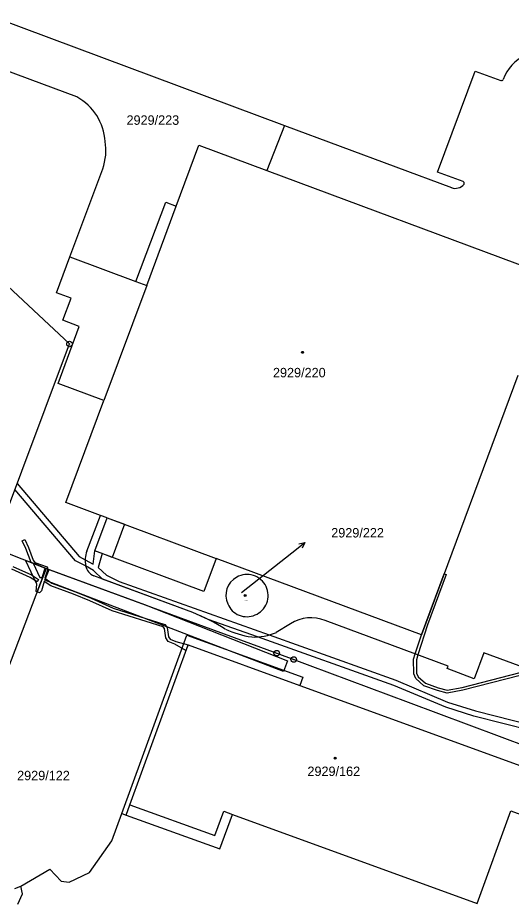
# Model space of a CAD drawing. Extents: x -593183 to -588034, y -1130415 to -1124994.
# Drawn here: x -591765.5 to -591676.7, y -1128297.1 to -1128137.6 of the extents above; entities that cross this region are included whole.
import ezdxf

# ---------------------------------------------------------------- set-up
doc = ezdxf.new("R2010")
doc.units = 0
for name, color, linetype in [('Vrstva 1', 7, 'Continuous'), ('Vrstva 16', 7, 'Continuous'), ('Vrstva 18', 7, 'Continuous'), ('Vrstva 19', 7, 'Continuous'), ('Vrstva 24', 7, 'Continuous'), ('Vrstva 25', 7, 'Continuous'), ('Vrstva 27', 7, 'Continuous'), ('Vrstva 4', 7, 'Continuous')]:
    doc.layers.add(name, color=color, linetype=linetype)

msp = doc.modelspace()

# ---------------------------------------------------------------- linework, layer by layer
at = {"layer": 'Vrstva 1'}
for p, q in [((-591717.5, -1128157.01), (-591720.69, -1128165.1)), ((-591717.5, -1128157.01), (-591687.51, -1128168.17)), ((-591717.5, -1128157.01), (-591687.51, -1128168.17)), ((-591717.5, -1128157.01), (-591687.51, -1128168.17)), ((-591737, -1128171.48), (-591732.94, -1128160.55)), ((-591732.94, -1128160.55), (-591720.69, -1128165.1)), ((-591756.14, -1128180.6), (-591750.22, -1128164.77)), ((-591756.14, -1128180.6), (-591750.22, -1128164.77)), ((-591756.14, -1128180.6), (-591750.22, -1128164.77)), ((-591720.69, -1128165.1), (-591669, -1128184.32)), ((-591782.19, -1128171.99), (-591756.21, -1128196.29)), ((-591758.54, -1128187.07), (-591756.14, -1128180.6)), ((-591756.14, -1128180.6), (-591744.27, -1128185.05)), ((-591755.89, -1128188.03), (-591758.54, -1128187.07)), ((-591757.38, -1128192.01), (-591755.89, -1128188.03)), ((-591754.44, -1128193.13), (-591757.38, -1128192.01)), ((-591758.22, -1128203.42), (-591754.44, -1128193.13)), ((-591769.95, -1128232.86), (-591756.21, -1128196.29)), ((-591675.56, -1128201.97), (-591692.89, -1128248.59)), ((-591750.02, -1128206.47), (-591758.22, -1128203.42)), ((-591756.84, -1128224.81), (-591750.02, -1128206.47)), ((-591750.6, -1128227.13), (-591756.84, -1128224.81)), ((-591753.08, -1128233.56), (-591750.6, -1128227.13)), ((-591751.66, -1128233.51), (-591749.41, -1128227.57)), ((-591749.41, -1128227.57), (-591750.6, -1128227.13)), ((-591769.95, -1128232.86), (-591760.42, -1128236.65)), ((-591732.03, -1128240.78), (-591751.66, -1128233.51)), ((-591729.84, -1128234.85), (-591732.03, -1128240.78)), ((-591692.89, -1128248.59), (-591729.84, -1128234.85)), ((-591768.44, -1128257.8), (-591760.42, -1128236.65)), ((-591760.42, -1128236.65), (-591718.92, -1128251.9)), ((-591733.99, -1128244.6), (-591751.81, -1128237.99)), ((-591733.99, -1128244.6), (-591751.81, -1128237.99)), ((-591733.99, -1128244.6), (-591751.81, -1128237.99)), ((-591716.43, -1128246.62), (-591719, -1128248.15)), ((-591716.43, -1128246.62), (-591719, -1128248.15)), ((-591716.43, -1128246.62), (-591719, -1128248.15)), ((-591716.43, -1128246.62), (-591719, -1128248.15)), ((-591745.34, -1128279.16), (-591734.87, -1128250.37)), ((-591734.87, -1128250.37), (-591714.78, -1128257.68)), ((-591718.92, -1128251.9), (-591715.86, -1128253.03)), ((-591715.86, -1128253.03), (-591712.99, -1128254.1)), ((-591712.99, -1128254.1), (-591695.28, -1128260.71)), ((-591714.78, -1128257.68), (-591668.38, -1128274.57)), ((-591695.28, -1128260.71), (-591673.48, -1128268.84)), ((-591746, -1128281.02), (-591745.34, -1128279.16)), ((-591748.57, -1128285.65), (-591746.78, -1128280.75)), ((-591746.78, -1128280.75), (-591746, -1128281.02)), ((-591746, -1128281.02), (-591729.15, -1128287.1)), ((-591729.15, -1128287.1), (-591726.89, -1128280.89)), ((-591726.89, -1128280.89), (-591682.86, -1128296.9)), ((-591682.86, -1128296.9), (-591676.8, -1128280.25)), ((-591676.8, -1128280.25), (-591671.21, -1128282.28)), ((-591752.63, -1128291.33), (-591748.57, -1128285.65)), ((-591764.94, -1128293.8), (-591759.76, -1128290.74)), ((-591759.76, -1128290.74), (-591757.68, -1128292.92)), ((-591756.24, -1128293.08), (-591752.63, -1128291.33)), ((-591764.68, -1128295.18), (-591764.94, -1128293.8)), ((-591757.68, -1128292.92), (-591756.24, -1128293.08)), ((-591765.52, -1128297.05), (-591764.68, -1128295.18))]:
    msp.add_line(p, q, dxfattribs=at)
for points in [[(-591754.86, -1128151.86), (-591772.23, -1128145.44), (-591769.48, -1128137.62), (-591717.5, -1128157.01)], [(-591685.4, -1128167.09), (-591689.98, -1128165.38), (-591683.2, -1128147.21), (-591678.61, -1128148.88)], [(-591685.4, -1128167.09), (-591689.98, -1128165.38), (-591683.2, -1128147.21), (-591678.61, -1128148.88)], [(-591685.4, -1128167.09), (-591689.98, -1128165.38), (-591683.2, -1128147.21), (-591678.61, -1128148.88)], [(-591744.27, -1128185.05), (-591738.9, -1128170.78), (-591737, -1128171.48)], [(-591744.27, -1128185.05), (-591738.9, -1128170.78), (-591737, -1128171.48)], [(-591744.27, -1128185.05), (-591738.9, -1128170.78), (-591737, -1128171.48)], [(-591744.27, -1128185.05), (-591738.9, -1128170.78), (-591737, -1128171.48)], [(-591744.27, -1128185.05), (-591738.9, -1128170.78), (-591737, -1128171.48)], [(-591681.67, -1128251.81), (-591683.41, -1128256.51), (-591688.27, -1128254.67), (-591688.09, -1128254.23), (-591710.22, -1128246.02)], [(-591681.67, -1128251.81), (-591683.41, -1128256.51), (-591688.27, -1128254.67), (-591688.09, -1128254.23), (-591710.22, -1128246.02)], [(-591640.13, -1128262.72), (-591641.52, -1128266.6), (-591681.67, -1128251.81)]]:
    msp.add_lwpolyline(points, dxfattribs=at)
for centre, radius, start, end in [((-591670.96, -1128151.26), 7.63, 71.7031, 160.6605), ((-591678.46, -1128148.58), 0.334, 243.1252, 333.7447), ((-591759.72, -1128160.54), 9.95, 3.8368, 60.7252), ((-591759.08, -1128161.54), 9.42, 339.9772, 10.2246), ((-591686.8, -1128166.29), 2.02, 249.2737, 321.4904), ((-591685.55, -1128167.41), 0.352, 338.3496, 65.2533), ((-591748.18, -1128235.31), 5.2, 160.3488, 189.6174), ((-591750.78, -1128235.61), 2.6, 192.7529, 246.5462), ((-591724.4, -1128241.45), 3.66, 118.1946, 205.3658), ((-591724.29, -1128241.59), 3.84, 25.8117, 118.6205), ((-591724.24, -1128241.53), 3.77, 292.1424, 25.2266), ((-591724.32, -1128241.7), 3.64, 201.2527, 294.2583), ((-591746.66, -1128276.61), 34.42, 57.5185, 68.4102), ((-591712.76, -1128252.2), 6.68, 67.6979, 123.3395), ((-591720.85, -1128231.64), 17.53, 245.3252, 261.5427), ((-591722.98, -1128239.12), 9.87, 267.4105, 293.8132)]:
    msp.add_arc(centre, radius, start, end, dxfattribs=at)
at = {"layer": 'Vrstva 16'}
msp.add_line((-591725.26, -1128240.98), (-591716.21, -1128233.85), dxfattribs=at)
at = {"layer": 'Vrstva 24'}
for centre, radius in [((-591756.21, -1128196.29), 0.5), ((-591756.21, -1128196.29), 0.0327), ((-591718.92, -1128251.9), 0.5), ((-591718.92, -1128251.9), 0.0327), ((-591715.86, -1128253.03), 0.5), ((-591715.86, -1128253.03), 0.0327)]:
    msp.add_circle(centre, radius, dxfattribs=at)
at = {"layer": 'Vrstva 25'}
msp.add_line((-591716.21, -1128233.85), (-591713.85, -1128231.99), dxfattribs=at)
msp.add_lwpolyline([(-591714.95, -1128232.22), (-591713.85, -1128231.99), (-591714.33, -1128233)], dxfattribs=at)
for centre, radius in [((-591714.27, -1128197.79), 0.175), ((-591714.27, -1128197.79), 0.15), ((-591724.6, -1128241.54), 0.175), ((-591724.6, -1128241.54), 0.15), ((-591708.43, -1128270.76), 0.175), ((-591708.43, -1128270.76), 0.15)]:
    msp.add_circle(centre, radius, dxfattribs=at)
at = {"layer": 'Vrstva 27'}
for p, q in [((-591765.64, -1128221.39), (-591754.49, -1128234.49)), ((-591755.13, -1128235.27), (-591766.04, -1128222.46)), ((-591751.66, -1128233.51), (-591749.41, -1128227.57)), ((-591749.41, -1128227.57), (-591746.32, -1128228.72)), ((-591746.32, -1128228.72), (-591748.52, -1128234.67)), ((-591764.69, -1128231.68), (-591764.24, -1128231.47)), ((-591764.04, -1128233.07), (-591764.69, -1128231.68)), ((-591764.24, -1128231.47), (-591763.58, -1128232.87)), ((-591763.08, -1128235.59), (-591764.04, -1128233.07)), ((-591763.58, -1128232.87), (-591762.71, -1128235.16)), ((-591754.49, -1128234.49), (-591753.38, -1128235.09)), ((-591753.38, -1128235.09), (-591751.92, -1128235.88)), ((-591751.92, -1128235.88), (-591751.66, -1128233.51)), ((-591750.35, -1128233.99), (-591751.05, -1128236.46)), ((-591748.52, -1128234.67), (-591750.35, -1128233.99)), ((-591766.38, -1128236.3), (-591763.02, -1128237.82)), ((-591762.11, -1128239.46), (-591764.1, -1128235.19)), ((-591764.1, -1128235.19), (-591763.08, -1128235.59)), ((-591763.08, -1128235.59), (-591762.75, -1128235.73)), ((-591762.75, -1128235.73), (-591763.08, -1128235.59)), ((-591762.75, -1128235.73), (-591761.56, -1128238.27)), ((-591760.59, -1128236.58), (-591762.75, -1128235.73)), ((-591762.71, -1128235.16), (-591762.42, -1128235.56)), ((-591762.42, -1128235.56), (-591760.23, -1128236.35)), ((-591760.42, -1128236.65), (-591762.02, -1128240.88)), ((-591762.02, -1128240.88), (-591760.42, -1128236.65)), ((-591761.14, -1128238.26), (-591760.59, -1128236.58)), ((-591760.59, -1128236.58), (-591760.42, -1128236.65)), ((-591760.42, -1128236.65), (-591760.59, -1128236.58)), ((-591760.13, -1128236.76), (-591760.42, -1128236.65)), ((-591760.42, -1128236.65), (-591760.13, -1128236.76)), ((-591760.23, -1128236.35), (-591760.13, -1128236.76)), ((-591753.31, -1128236.18), (-591755.13, -1128235.27)), ((-591751.91, -1128237.03), (-591753.31, -1128236.18)), ((-591751.05, -1128236.46), (-591749.52, -1128237.89)), ((-591763.26, -1128238.26), (-591766.58, -1128236.76)), ((-591762.05, -1128239.05), (-591763.26, -1128238.26)), ((-591763.02, -1128237.82), (-591761.77, -1128238.63)), ((-591761.56, -1128238.27), (-591761.14, -1128238.26)), ((-591760.13, -1128236.76), (-591760.67, -1128238.41)), ((-591760.63, -1128238.74), (-591759.89, -1128236.84)), ((-591759.89, -1128236.84), (-591742.73, -1128243.15)), ((-591750.29, -1128238.56), (-591751.91, -1128237.03)), ((-591749.52, -1128237.89), (-591747.26, -1128238.98)), ((-591692.89, -1128248.59), (-591688.81, -1128237.63)), ((-591688.44, -1128237.77), (-591691.79, -1128246.79)), ((-591688.81, -1128237.63), (-591688.44, -1128237.77)), ((-591762.21, -1128240.81), (-591762.11, -1128239.46)), ((-591761.77, -1128238.63), (-591762.05, -1128239.05)), ((-591760.76, -1128239.03), (-591761.22, -1128240.7)), ((-591759.59, -1128239.77), (-591760.76, -1128239.03)), ((-591760.67, -1128238.41), (-591759.37, -1128239.31)), ((-591717.7, -1128255.17), (-591760.63, -1128238.74)), ((-591755.51, -1128241.26), (-591759.59, -1128239.77)), ((-591759.37, -1128239.31), (-591755.33, -1128240.8)), ((-591733.99, -1128244.6), (-591750.29, -1128238.56)), ((-591747.26, -1128238.98), (-591720.3, -1128248.62)), ((-591762.02, -1128240.88), (-591762.21, -1128240.81)), ((-591761.62, -1128241.04), (-591762.02, -1128240.88)), ((-591761.22, -1128240.7), (-591761.62, -1128241.04)), ((-591752.52, -1128242.46), (-591755.51, -1128241.26)), ((-591755.33, -1128240.8), (-591752.32, -1128242)), ((-591748.54, -1128244.27), (-591752.52, -1128242.46)), ((-591752.32, -1128242), (-591748.36, -1128243.81)), ((-591739.35, -1128247.15), (-591748.54, -1128244.27)), ((-591748.36, -1128243.81), (-591739.07, -1128246.71)), ((-591742.73, -1128243.15), (-591716.98, -1128253.26)), ((-591731.24, -1128245.83), (-591733.99, -1128244.6)), ((-591722.41, -1128248.97), (-591731.24, -1128245.83)), ((-591739.1, -1128247.45), (-591739.35, -1128247.15)), ((-591738.88, -1128249.11), (-591739.1, -1128247.45)), ((-591739.07, -1128246.71), (-591738.62, -1128247.25)), ((-591738.62, -1128247.25), (-591738.4, -1128248.93)), ((-591691.79, -1128246.79), (-591693.52, -1128252.22)), ((-591738.46, -1128249.78), (-591738.88, -1128249.11)), ((-591738.4, -1128248.93), (-591738.12, -1128249.38)), ((-591738.12, -1128249.38), (-591737.08, -1128249.82)), ((-591697.88, -1128257.7), (-591722.41, -1128248.97)), ((-591720.3, -1128248.62), (-591697.52, -1128256.76)), ((-591693.99, -1128252.04), (-591692.89, -1128248.59)), ((-591737.28, -1128250.28), (-591738.46, -1128249.78)), ((-591735.26, -1128251.44), (-591737.28, -1128250.28)), ((-591737.08, -1128249.82), (-591734.87, -1128250.37)), ((-591734.87, -1128250.37), (-591735.26, -1128251.44)), ((-591694.29, -1128253), (-591693.99, -1128252.04)), ((-591693.52, -1128252.22), (-591693.79, -1128253.08)), ((-591716.98, -1128253.26), (-591717.7, -1128255.17)), ((-591694.25, -1128255.62), (-591694.29, -1128253)), ((-591693.79, -1128253.08), (-591693.75, -1128255.5)), ((-591693.87, -1128256.47), (-591694.25, -1128255.62)), ((-591693.75, -1128255.5), (-591693.45, -1128256.17)), ((-591685.57, -1128258.08), (-591675.15, -1128255.37)), ((-591697.52, -1128256.76), (-591688.19, -1128260.68)), ((-591692.44, -1128257.75), (-591693.87, -1128256.47)), ((-591693.45, -1128256.17), (-591692.18, -1128257.31)), ((-591692.18, -1128257.31), (-591689.86, -1128258.15)), ((-591675.13, -1128255.89), (-591685.47, -1128258.56)), ((-591688.53, -1128261.62), (-591697.88, -1128257.7)), ((-591690, -1128258.63), (-591692.44, -1128257.75)), ((-591688.27, -1128259.06), (-591690, -1128258.63)), ((-591689.86, -1128258.15), (-591688.25, -1128258.54)), ((-591685.47, -1128258.56), (-591688.27, -1128259.06)), ((-591688.25, -1128258.54), (-591685.57, -1128258.08)), ((-591683.47, -1128263.25), (-591688.53, -1128261.62)), ((-591688.19, -1128260.68), (-591683.19, -1128262.29)), ((-591672.26, -1128266.06), (-591683.47, -1128263.25)), ((-591683.19, -1128262.29), (-591672.08, -1128265.08))]:
    msp.add_line(p, q, dxfattribs=at)
at = {"layer": 'Vrstva 4'}
for p, q in [((-591742.32, -1128185.78), (-591737, -1128171.48)), ((-591744.27, -1128185.05), (-591742.32, -1128185.78)), ((-591742.32, -1128185.78), (-591750.02, -1128206.47)), ((-591749.41, -1128227.57), (-591729.84, -1128234.85)), ((-591743.06, -1128270.54), (-591735.07, -1128248.66)), ((-591735.07, -1128248.66), (-591714.25, -1128256.2)), ((-591714.25, -1128256.2), (-591714.78, -1128257.68)), ((-591746.78, -1128280.75), (-591743.06, -1128270.54)), ((-591745.34, -1128279.16), (-591730.05, -1128284.69)), ((-591730.05, -1128284.69), (-591728.45, -1128280.33)), ((-591728.45, -1128280.33), (-591726.89, -1128280.89)), ((-591766.01, -1128294.21), (-591764.94, -1128293.8))]:
    msp.add_line(p, q, dxfattribs=at)

# ---------------------------------------------------------------- texts
at = {"layer": 'Vrstva 16'}
msp.add_text('2929/222', height=1.7, dxfattribs=at).set_placement((-591709.12, -1128231.09))
at = {"layer": 'Vrstva 18'}
for s, p in [('2929/223', (-591745.95, -1128156.88)), ('2929/122', (-591765.63, -1128274.75))]:
    msp.add_text(s, height=1.7, dxfattribs=at).set_placement(p)
at = {"layer": 'Vrstva 19'}
for s, height, p in [('2929/220', 1.7, (-591719.6, -1128202.29)), ('2929/222', 0.1, (-591724.71, -1128242.43)), ('2929/162', 1.7, (-591713.4, -1128273.99))]:
    msp.add_text(s, height=height, dxfattribs=at).set_placement(p)

doc.saveas('drawing.dxf')
